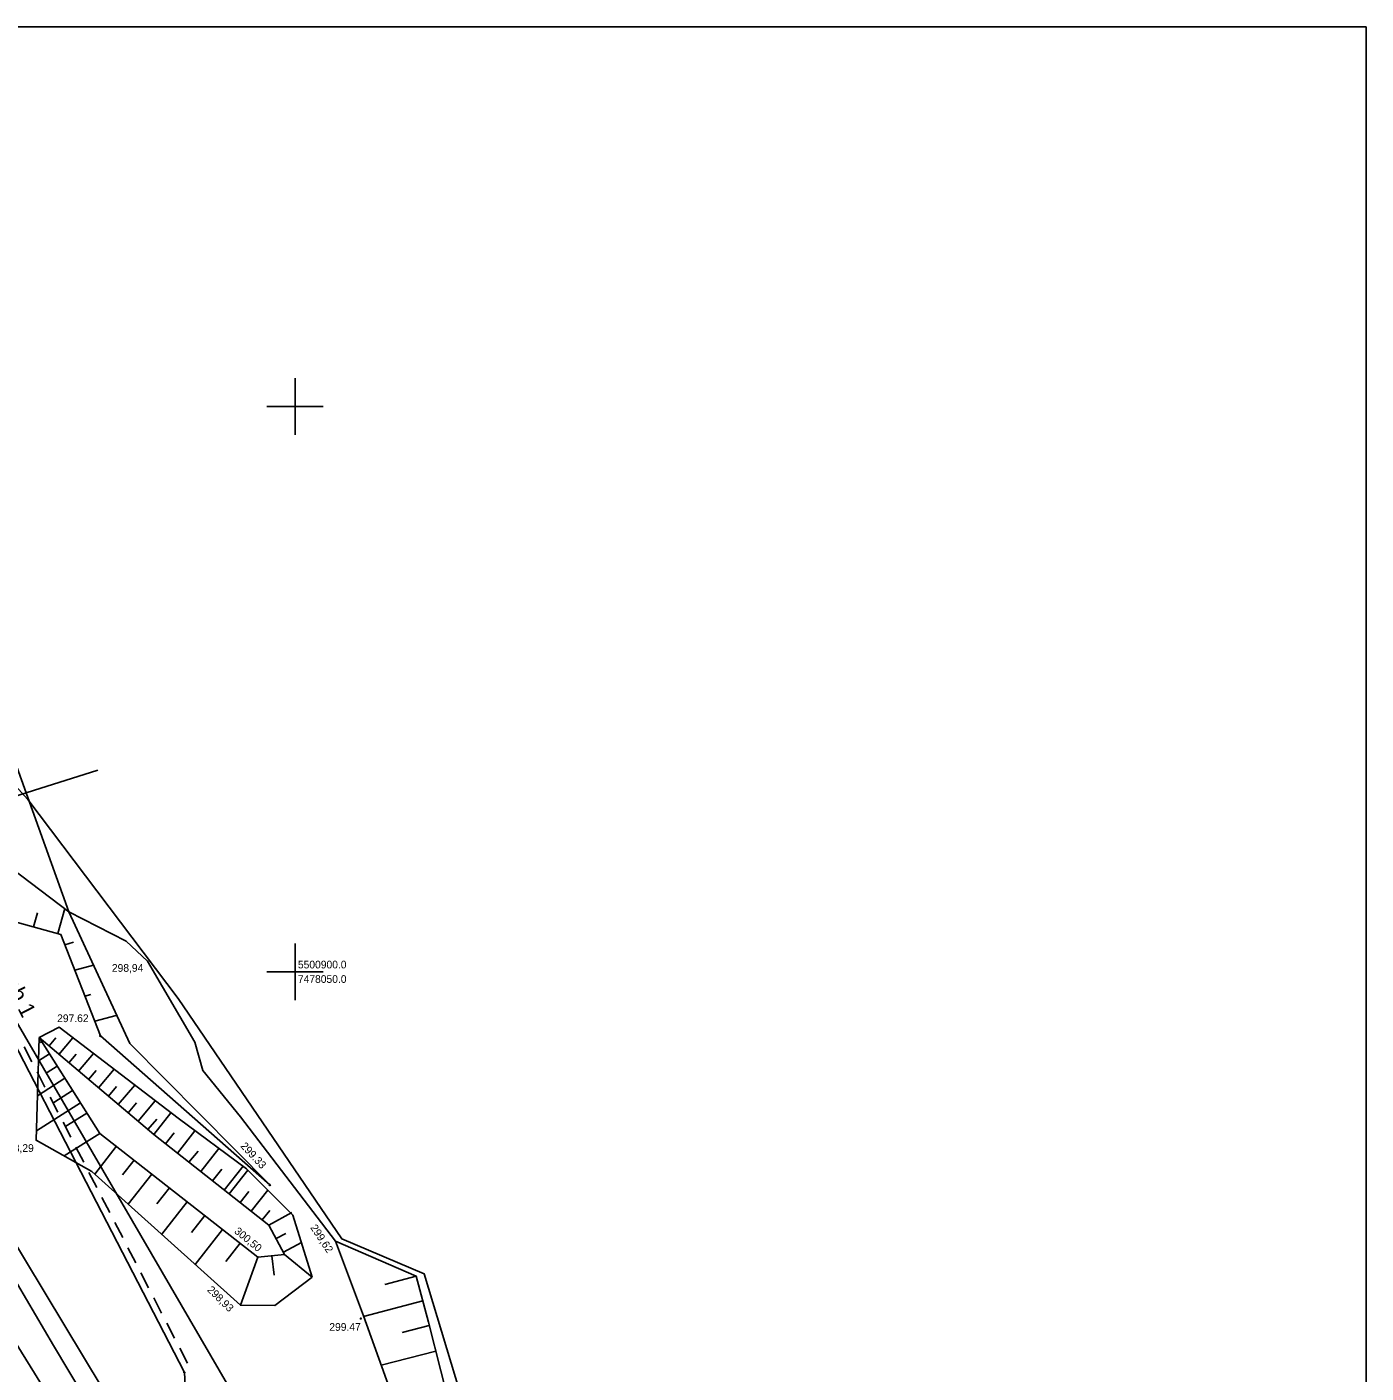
# Model space of a CAD drawing. Extents: x 7477803 to 7478145, y 5500698 to 5500984.
# Drawn here: x 7478026.3 to 7478144.7, y 5500864.5 to 5500983.6 of the extents above; entities that cross this region are included whole.
import ezdxf

# ---------------------------------------------------------------- set-up
doc = ezdxf.new("R2010")
doc.units = 0
for name, color, linetype in [('203-Punkt załamania granicy działki nie stabilizowany', 7, 'Continuous'), ('gr_dzialki', 7, 'Continuous'), ('gr_klasy', 7, 'Continuous'), ('k', 7, 'Continuous'), ('nr_obrebu', 7, 'Continuous'), ('pkt_wys', 7, 'Continuous'), ('pob_gr_obrebu', 7, 'Continuous'), ('robocza11', 7, 'Continuous'), ('robocza49', 7, 'Continuous'), ('robocza50', 7, 'Continuous'), ('skarp_wypel', 7, 'Continuous'), ('skarpa_dol', 7, 'Continuous'), ('skarpa_gora', 7, 'Continuous'), ('w', 7, 'Continuous'), ('zakresy', 7, 'Continuous')]:
    doc.layers.add(name, color=color, linetype=linetype)

# ---------------------------------------------------------------- blocks, each defined once
blk = doc.blocks.new('203')
blk.add_circle((0, 0), 0.045)
blk = doc.blocks.new('801_5')
at = {"layer": 'pkt_wys'}
blk.add_circle((0, 0), 0.05, dxfattribs=at)
blk.add_circle((0, 0), 0.05, dxfattribs=at)
blk = doc.blocks.new('801_5_4')
at = {"layer": 'pkt_wys'}
blk.add_circle((0, 0), 0.05, dxfattribs=at)
blk.add_circle((0, 0), 0.05, dxfattribs=at)

msp = doc.modelspace()

# ---------------------------------------------------------------- linework, layer by layer
at = {"layer": 'gr_dzialki'}
for points in [[(7478015.47, 5500912.43), (7478032.56, 5500917.83)], [(7478040.21, 5500864.57), (7478015.47, 5500912.43)], [(7478040.72, 5500854.66), (7478040.21, 5500864.57)]]:
    msp.add_lwpolyline(points, dxfattribs=at)
at = {"layer": 'gr_klasy'}
for points in [[(7477998.73, 5500919.96), (7478036.42, 5500857.42)], [(7478027.95, 5500862.87), (7477997.16, 5500912.65)], [(7478040.21, 5500864.57), (7478015.47, 5500912.43)], [(7478040.72, 5500854.66), (7478040.21, 5500864.57)]]:
    msp.add_lwpolyline(points, dxfattribs=at)
at = {"layer": 'k'}
msp.add_lwpolyline([(7478020.44, 5500904), (7478021.75, 5500901.76), (7478045.91, 5500860.25)], dxfattribs=at)
at = {"layer": 'pob_gr_obrebu'}
for p, q in [((7478026.03, 5500893.36), (7478026.72, 5500892.03)), ((7478027.18, 5500891.14), (7478027.87, 5500889.81)), ((7478028.33, 5500888.92), (7478029.02, 5500887.59)), ((7478029.48, 5500886.7), (7478030.17, 5500885.37)), ((7478030.62, 5500884.48), (7478031.31, 5500883.15)), ((7478031.77, 5500882.26), (7478032.46, 5500880.93)), ((7478032.92, 5500880.04), (7478033.61, 5500878.71)), ((7478034.07, 5500877.82), (7478034.76, 5500876.49)), ((7478035.22, 5500875.6), (7478035.91, 5500874.27)), ((7478036.36, 5500873.38), (7478037.05, 5500872.05)), ((7478037.51, 5500871.16), (7478038.2, 5500869.82)), ((7478038.66, 5500868.94), (7478039.35, 5500867.6)), ((7478039.81, 5500866.72), (7478040.5, 5500865.38))]:
    msp.add_line(p, q, dxfattribs=at)
at = {"layer": 'robocza11'}
msp.add_lwpolyline([(7478015, 5500697.57), (7478144.73, 5500697.57), (7478144.73, 5500983.57), (7477803.26, 5500983.57), (7477803.26, 5500697.57), (7478010.82, 5500697.57)], close=True, dxfattribs=at)
at = {"layer": 'robocza49'}
for p, q in [((7478050, 5500947.5), (7478050, 5500952.5)), ((7478047.5, 5500950), (7478052.5, 5500950)), ((7478050, 5500897.5), (7478050, 5500902.5)), ((7478047.5, 5500900), (7478052.5, 5500900))]:
    msp.add_line(p, q, dxfattribs=at)
at = {"layer": 'skarp_wypel'}
for p, q in [((7478029.03, 5500903.38), (7478029.64, 5500905.59)), ((7478026.88, 5500903.97), (7478027.22, 5500905.23)), ((7478029.64, 5500902.4), (7478030.41, 5500902.61)), ((7478030.52, 5500900.14), (7478032.16, 5500900.59)), ((7478031.42, 5500897.85), (7478031.94, 5500897.99)), ((7478032.28, 5500895.62), (7478034.19, 5500896.14)), ((7478027.59, 5500893.83), (7478027.47, 5500893.75)), ((7478028.24, 5500893.44), (7478028.85, 5500894.15)), ((7478029.12, 5500892.7), (7478030.35, 5500894.16)), ((7478028.28, 5500892.74), (7478027.31, 5500892.13)), ((7478029.99, 5500891.96), (7478030.63, 5500892.72)), ((7478030.86, 5500891.22), (7478032.18, 5500892.77)), ((7478028.96, 5500891.66), (7478028.07, 5500891.1)), ((7478031.74, 5500890.48), (7478032.42, 5500891.28)), ((7478032.61, 5500889.74), (7478034, 5500891.38)), ((7478029.65, 5500890.58), (7478027.22, 5500889.04)), ((7478030.33, 5500889.5), (7478028.68, 5500888.45)), ((7478033.49, 5500889), (7478034.2, 5500889.85)), ((7478034.36, 5500888.26), (7478035.82, 5500889.98)), ((7478031.02, 5500888.41), (7478027.13, 5500885.95)), ((7478035.23, 5500887.52), (7478035.99, 5500888.41)), ((7478036.11, 5500886.78), (7478037.64, 5500888.59)), ((7478031.59, 5500887.51), (7478029.64, 5500886.28)), ((7478036.98, 5500886.04), (7478037.77, 5500886.98)), ((7478037.51, 5500885.6), (7478039.02, 5500887.52)), ((7478032.74, 5500885.7), (7478029.59, 5500883.71)), ((7478038.55, 5500884.78), (7478039.32, 5500885.76)), ((7478039.59, 5500883.96), (7478041.15, 5500885.95)), ((7478034.19, 5500884.56), (7478032.28, 5500882.11)), ((7478040.62, 5500883.15), (7478041.42, 5500884.15)), ((7478041.66, 5500882.33), (7478043.27, 5500884.37)), ((7478035.76, 5500883.34), (7478034.74, 5500882.04)), ((7478037.33, 5500882.11), (7478035.24, 5500879.45)), ((7478042.7, 5500881.51), (7478043.52, 5500882.55)), ((7478043.74, 5500880.69), (7478045.4, 5500882.8)), ((7478044.16, 5500880.36), (7478045.81, 5500882.46)), ((7478038.89, 5500880.89), (7478037.79, 5500879.48)), ((7478045.14, 5500879.59), (7478045.92, 5500880.58)), ((7478046.12, 5500878.82), (7478047.59, 5500880.69)), ((7478040.46, 5500879.66), (7478038.21, 5500876.79)), ((7478042.02, 5500878.44), (7478040.84, 5500876.93)), ((7478047.1, 5500878.05), (7478047.78, 5500878.9)), ((7478047.68, 5500877.6), (7478049.72, 5500878.71)), ((7478043.59, 5500877.22), (7478041.17, 5500874.12)), ((7478045.15, 5500875.99), (7478043.89, 5500874.37)), ((7478048.33, 5500876.4), (7478049.19, 5500876.87)), ((7478048.98, 5500875.2), (7478050.56, 5500876.05)), ((7478046.72, 5500874.77), (7478045.17, 5500870.53)), ((7478047.96, 5500874.89), (7478048.14, 5500873.16)), ((7478049.08, 5500875.01), (7478051.52, 5500872.99)), ((7478060.72, 5500873.09), (7478057.95, 5500872.36)), ((7478061.3, 5500870.9), (7478056.05, 5500869.52)), ((7478061.87, 5500868.72), (7478059.46, 5500868.09)), ((7478062.45, 5500866.44), (7478057.61, 5500865.21))]:
    msp.add_line(p, q, dxfattribs=at)
at = {"layer": 'skarpa_dol'}
for points in [[(7478085.67, 5500829.13), (7478082.04, 5500830.41), (7478076.06, 5500834.55), (7478068.12, 5500840.29), (7478063.17, 5500845.24), (7478061.74, 5500849.74), (7478060.4, 5500857.52), (7478056.04, 5500869.57), (7478053.57, 5500876.19), (7478045.19, 5500887.17), (7478041.83, 5500891.27), (7478041.13, 5500893.79), (7478036.96, 5500900.93), (7478035.06, 5500902.7), (7478030, 5500905.29)], [(7478051.52, 5500872.99), (7478049.8, 5500878.48), (7478045.71, 5500882.57), (7478039.66, 5500887.05), (7478029.13, 5500895.1), (7478027.37, 5500894.18)], [(7478051.52, 5500872.99), (7478048.2, 5500870.48), (7478045.17, 5500870.53), (7478032.02, 5500882.34), (7478027.11, 5500885.1), (7478027.37, 5500894.18)]]:
    msp.add_lwpolyline(points, dxfattribs=at)
at = {"layer": 'skarpa_gora'}
for p, q in [((7478025.25, 5500918.53), (7478030, 5500905.29)), ((7478031.02, 5500888.41), (7478027.37, 5500894.18))]:
    msp.add_line(p, q, dxfattribs=at)
for points in [[(7478007.88, 5500866.79), (7478009.36, 5500868.17), (7477985.35, 5500883.4), (7477939.9, 5500913.11), (7477944.56, 5500919.79), (7477954.95, 5500928.71), (7477971.01, 5500935.43), (7477981.22, 5500940.41), (7477991.64, 5500944.91), (7477994.87, 5500942.92), (7478002.78, 5500931.77), (7478021.27, 5500905.52), (7478029.29, 5500903.31), (7478032.78, 5500894.33), (7478047.77, 5500881.15)], [(7478047.77, 5500881.15), (7478035.39, 5500893.66), (7478030, 5500905.29), (7478021.54, 5500911.71), (7478015.07, 5500924.49)], [(7478027.37, 5500894.18), (7478037.51, 5500885.6), (7478047.68, 5500877.6), (7478049.08, 5500875.01), (7478046.72, 5500874.77), (7478032.74, 5500885.7), (7478027.37, 5500894.18)], [(7478084.59, 5500831.42), (7478082.61, 5500832.72), (7478075.68, 5500837.65), (7478072.57, 5500841.44), (7478069.56, 5500846.97), (7478067.13, 5500850.64), (7478065.08, 5500856.09), (7478061.8, 5500869.01), (7478060.72, 5500873.09), (7478053.57, 5500876.19)]]:
    msp.add_lwpolyline(points, dxfattribs=at)
at = {"layer": 'w'}
msp.add_lwpolyline([(7478024.65, 5500873.72), (7478028.65, 5500866.94), (7478037.87, 5500851.49), (7478050.77, 5500839.57), (7478051.32, 5500839.07), (7478052.9, 5500837.63)], dxfattribs=at)
at = {"layer": 'zakresy'}
msp.add_lwpolyline([(7477995.06, 5500962.35), (7477983.95, 5500968.08), (7477970.78, 5500968.61), (7477936.09, 5500958.17), (7477930.51, 5500954.34), (7477914.3, 5500958.58), (7477904.32, 5500957.41), (7477897.27, 5500950.87), (7477811.42, 5500829.34), (7477936, 5500769.49), (7478008.98, 5500726.58), (7478019.4, 5500721.78), (7478037.95, 5500734.97), (7478039.49, 5500755.09), (7478043.98, 5500765.71), (7478067.54, 5500795.07), (7478092.11, 5500820.25), (7478076.16, 5500837.99), (7478068.11, 5500851.15), (7478061.42, 5500873.3), (7478054.13, 5500876.37), (7478039.67, 5500897.64), (7478026.36, 5500915.23), (7478015.05, 5500927.73)], close=True, dxfattribs=at)

# ---------------------------------------------------------------- block references
at = {"layer": '203-Punkt załamania granicy działki nie stabilizowany'}
msp.add_blockref('203', (7478040.21, 5500864.57), dxfattribs=at)
at = {"layer": 'pkt_wys', "xscale": 0.25, "yscale": 0.24999999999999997, "rotation": 0.0626175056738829}
for p in [(7478036.96, 5500900.93), (7478027.11, 5500885.1), (7478053.57, 5500876.19), (7478046.72, 5500874.77), (7478045.17, 5500870.53)]:
    msp.add_blockref('801_5_4', p, dxfattribs=at)
at = {"layer": 'pkt_wys', "rotation": 0.0626175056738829}
for p in [(7478032.78, 5500894.33), (7478047.77, 5500881.15), (7478055.82, 5500869.33)]:
    msp.add_blockref('801_5', p, dxfattribs=at)

# ---------------------------------------------------------------- texts
at = {"layer": 'nr_obrebu'}
msp.add_text('obręb 1', height=1.4, rotation=297.1657, dxfattribs=at).set_placement((7478023.01, 5500901.49))
at = {"layer": 'pkt_wys'}
for s, rotation, p in [('298,94', 0.0626, (7478033.8, 5500900)), ('297.62', 0.0626, (7478028.96, 5500895.55)), ('298,29', 0.0626, (7478024.11, 5500884.07)), ('299.33', 312.9741, (7478045.13, 5500884.55)), ('300,50', 320.3589, (7478044.57, 5500876.96)), ('299,62', 303.576, (7478051.32, 5500877.38)), ('298,93', 315.6472, (7478042.18, 5500871.81)), ('299.47', 0.0626, (7478053.03, 5500868.25))]:
    msp.add_text(s, height=0.68, rotation=rotation, dxfattribs=at).set_placement(p)
at = {"layer": 'robocza50'}
for s, p in [(' 5500900.0', (7478050, 5500900.3)), (' 7478050.0', (7478050, 5500899.02))]:
    msp.add_text(s, height=0.68, dxfattribs=at).set_placement(p)

doc.saveas('drawing.dxf')
